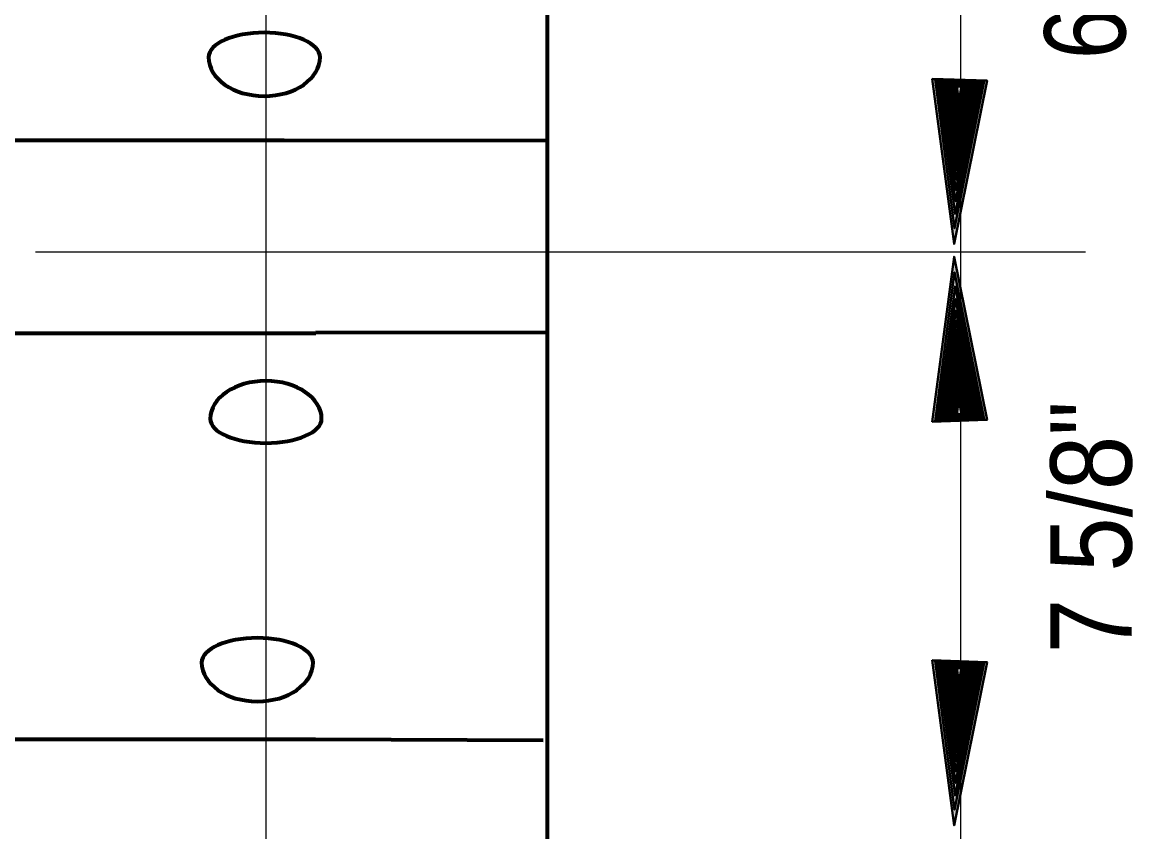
# Model space of a CAD drawing. Extents: x 895.6 to 930.4, y -2278.6 to -2254.7.
# Drawn here: x 918.313 to 920.071, y -2272.9 to -2271.618 of the extents above; entities that cross this region are included whole.
import ezdxf

# ---------------------------------------------------------------- set-up
doc = ezdxf.new("R2010")
doc.units = 0
doc.header["$LTSCALE"] = 0.051
doc.layers.add('1', color=7, linetype='Continuous', lineweight=70)
doc.layers.add('3', color=7, linetype='Continuous', lineweight=40)

msp = doc.modelspace()

# ---------------------------------------------------------------- hatches: boundary and pattern name
at = {"layer": '3'}
for points in [[(919.75367, -2271.708), (919.84033, -2271.71092), (919.78817, -2271.96933), (919.78817, -2271.96933)], [(919.758, -2271.70925), (919.836, -2271.712), (919.789, -2271.94458), (919.789, -2271.94458)], [(919.76192, -2271.7105), (919.832, -2271.71283), (919.78975, -2271.92217), (919.78975, -2271.92217)], [(919.76533, -2271.7115), (919.82842, -2271.71367), (919.79042, -2271.90217), (919.79042, -2271.90217)], [(919.76833, -2271.71242), (919.82517, -2271.71433), (919.791, -2271.88408), (919.791, -2271.88408)], [(919.77125, -2271.7135), (919.82233, -2271.71508), (919.7915, -2271.86783), (919.7915, -2271.86783)], [(919.77383, -2271.71417), (919.81975, -2271.71567), (919.792, -2271.85308), (919.792, -2271.85308)], [(919.776, -2271.715), (919.8175, -2271.71625), (919.7925, -2271.83983), (919.7925, -2271.83983)], [(919.778, -2271.71542), (919.81542, -2271.71675), (919.793, -2271.82808), (919.793, -2271.82808)], [(919.78, -2271.71617), (919.81367, -2271.71733), (919.79333, -2271.81725), (919.79333, -2271.81725)], [(919.7815, -2271.71658), (919.81183, -2271.71767), (919.79358, -2271.80767), (919.79358, -2271.80767)], [(919.78308, -2271.71708), (919.81025, -2271.71808), (919.794, -2271.79908), (919.794, -2271.79908)], [(919.78442, -2271.7175), (919.80892, -2271.71833), (919.79425, -2271.79117), (919.79425, -2271.79117)], [(919.78567, -2271.71808), (919.80775, -2271.71858), (919.79442, -2271.78425), (919.79442, -2271.78425)], [(919.78675, -2271.71825), (919.80658, -2271.71892), (919.79458, -2271.778), (919.79458, -2271.778)], [(919.78775, -2271.71867), (919.80558, -2271.71908), (919.79492, -2271.77233), (919.79492, -2271.77233)], [(919.78867, -2271.71883), (919.80475, -2271.71942), (919.79508, -2271.76725), (919.79508, -2271.76725)], [(919.7895, -2271.719), (919.80392, -2271.71958), (919.79525, -2271.76267), (919.79525, -2271.76267)], [(919.78992, -2271.71942), (919.80308, -2271.71967), (919.79525, -2271.75858), (919.79525, -2271.75858)], [(919.7905, -2271.71958), (919.80233, -2271.72), (919.79533, -2271.75492), (919.79533, -2271.75492)], [(919.791, -2271.71992), (919.80158, -2271.72033), (919.79517, -2271.75167), (919.79517, -2271.75167)], [(919.79158, -2271.71992), (919.801, -2271.72033), (919.79533, -2271.74858), (919.79533, -2271.74858)], [(919.79208, -2271.72008), (919.80058, -2271.72042), (919.79558, -2271.74583), (919.79558, -2271.74583)], [(919.7925, -2271.72033), (919.80008, -2271.7205), (919.7955, -2271.7435), (919.7955, -2271.7435)], [(919.75367, -2272.25083), (919.84033, -2272.24792), (919.78817, -2271.9895), (919.78817, -2271.9895)], [(919.758, -2272.24958), (919.836, -2272.24683), (919.789, -2272.01425), (919.789, -2272.01425)], [(919.76192, -2272.24833), (919.832, -2272.246), (919.78975, -2272.03667), (919.78975, -2272.03667)], [(919.76533, -2272.24733), (919.82842, -2272.24517), (919.79042, -2272.05667), (919.79042, -2272.05667)], [(919.76833, -2272.24642), (919.82517, -2272.2445), (919.791, -2272.07475), (919.791, -2272.07475)], [(919.77125, -2272.24533), (919.82233, -2272.24375), (919.7915, -2272.091), (919.7915, -2272.091)], [(919.77383, -2272.24467), (919.81975, -2272.24317), (919.792, -2272.10575), (919.792, -2272.10575)], [(919.776, -2272.24383), (919.8175, -2272.24258), (919.7925, -2272.119), (919.7925, -2272.119)], [(919.778, -2272.24342), (919.81542, -2272.24208), (919.793, -2272.13075), (919.793, -2272.13075)], [(919.78, -2272.24267), (919.81367, -2272.2415), (919.79333, -2272.14158), (919.79333, -2272.14158)], [(919.7815, -2272.24225), (919.81183, -2272.24117), (919.79358, -2272.15117), (919.79358, -2272.15117)], [(919.78308, -2272.24175), (919.81025, -2272.24075), (919.794, -2272.15975), (919.794, -2272.15975)], [(919.78442, -2272.24133), (919.80892, -2272.2405), (919.79425, -2272.16767), (919.79425, -2272.16767)], [(919.78567, -2272.24075), (919.80775, -2272.24025), (919.79442, -2272.17458), (919.79442, -2272.17458)], [(919.78675, -2272.24058), (919.80658, -2272.23992), (919.79458, -2272.18083), (919.79458, -2272.18083)], [(919.78775, -2272.24017), (919.80558, -2272.23975), (919.79492, -2272.1865), (919.79492, -2272.1865)], [(919.78867, -2272.24), (919.80475, -2272.23942), (919.79508, -2272.19158), (919.79508, -2272.19158)], [(919.7895, -2272.23983), (919.80392, -2272.23925), (919.79525, -2272.19617), (919.79525, -2272.19617)], [(919.78992, -2272.23942), (919.80308, -2272.23917), (919.79525, -2272.20025), (919.79525, -2272.20025)], [(919.7905, -2272.23925), (919.80233, -2272.23883), (919.79533, -2272.20392), (919.79533, -2272.20392)], [(919.791, -2272.23892), (919.80158, -2272.2385), (919.79517, -2272.20717), (919.79517, -2272.20717)], [(919.79158, -2272.23892), (919.801, -2272.2385), (919.79533, -2272.21025), (919.79533, -2272.21025)], [(919.79208, -2272.23875), (919.80058, -2272.23842), (919.79558, -2272.213), (919.79558, -2272.213)], [(919.7925, -2272.2385), (919.80008, -2272.23833), (919.7955, -2272.21533), (919.7955, -2272.21533)], [(919.75367, -2272.62817), (919.84033, -2272.63108), (919.78817, -2272.8895), (919.78817, -2272.8895)], [(919.758, -2272.62942), (919.836, -2272.63217), (919.789, -2272.86475), (919.789, -2272.86475)], [(919.76192, -2272.63067), (919.832, -2272.633), (919.78975, -2272.84233), (919.78975, -2272.84233)], [(919.76533, -2272.63167), (919.82842, -2272.63383), (919.79042, -2272.82233), (919.79042, -2272.82233)], [(919.76833, -2272.63258), (919.82517, -2272.6345), (919.791, -2272.80425), (919.791, -2272.80425)], [(919.77125, -2272.63367), (919.82233, -2272.63525), (919.7915, -2272.788), (919.7915, -2272.788)], [(919.77383, -2272.63433), (919.81975, -2272.63583), (919.792, -2272.77325), (919.792, -2272.77325)], [(919.776, -2272.63517), (919.8175, -2272.63642), (919.7925, -2272.76), (919.7925, -2272.76)], [(919.778, -2272.63558), (919.81542, -2272.63692), (919.793, -2272.74825), (919.793, -2272.74825)], [(919.78, -2272.63633), (919.81367, -2272.6375), (919.79333, -2272.73742), (919.79333, -2272.73742)], [(919.7815, -2272.63675), (919.81183, -2272.63783), (919.79358, -2272.72783), (919.79358, -2272.72783)], [(919.78308, -2272.63725), (919.81025, -2272.63825), (919.794, -2272.71925), (919.794, -2272.71925)], [(919.78442, -2272.63767), (919.80892, -2272.6385), (919.79425, -2272.71133), (919.79425, -2272.71133)], [(919.78567, -2272.63825), (919.80775, -2272.63875), (919.79442, -2272.70442), (919.79442, -2272.70442)], [(919.78675, -2272.63842), (919.80658, -2272.63908), (919.79458, -2272.69817), (919.79458, -2272.69817)], [(919.78775, -2272.63883), (919.80558, -2272.63925), (919.79492, -2272.6925), (919.79492, -2272.6925)], [(919.78867, -2272.639), (919.80475, -2272.63958), (919.79508, -2272.68742), (919.79508, -2272.68742)], [(919.7895, -2272.63917), (919.80392, -2272.63975), (919.79525, -2272.68283), (919.79525, -2272.68283)], [(919.78992, -2272.63958), (919.80308, -2272.63983), (919.79525, -2272.67875), (919.79525, -2272.67875)], [(919.7905, -2272.63975), (919.80233, -2272.64017), (919.79533, -2272.67508), (919.79533, -2272.67508)], [(919.791, -2272.64008), (919.80158, -2272.6405), (919.79517, -2272.67183), (919.79517, -2272.67183)], [(919.79158, -2272.64008), (919.801, -2272.6405), (919.79533, -2272.66875), (919.79533, -2272.66875)], [(919.79208, -2272.64025), (919.80058, -2272.64058), (919.79558, -2272.666), (919.79558, -2272.666)], [(919.7925, -2272.6405), (919.80008, -2272.64067), (919.7955, -2272.66367), (919.7955, -2272.66367)]]:
    msp.add_hatch(color=256, dxfattribs=at).paths.add_polyline_path(points)

# ---------------------------------------------------------------- linework, layer by layer
at = {"layer": '1', "lineweight": 25}
for p, q in [((918.69942, -2273.34217), (918.69942, -2270.69617)), ((919.79892, -2273.84467), (919.79892, -2271.02042)), ((918.33392, -2271.98208), (919.99592, -2271.98208))]:
    msp.add_line(p, q, dxfattribs=at)
at = {"layer": '1'}
for p, q in [((919.14467, -2273.83717), (919.14467, -2271.04083)), ((918.77767, -2272.111), (917.28567, -2272.111)), ((919.142, -2272.10983), (918.77767, -2272.1095))]:
    msp.add_line(p, q, dxfattribs=at)
for points in [[(917.2355, -2271.80542), (917.23517, -2271.80533), (918.72717, -2271.80533), (919.14617, -2271.80583)], [(917.28467, -2272.75292), (918.77667, -2272.75292), (919.13792, -2272.75483)]]:
    msp.add_lwpolyline(points, dxfattribs=at)
for centre, major_axis, ratio in [((918.69626, -2271.6739), (-0.08819, 0), 0.442883), ((918.69626, -2271.6739), (0.08819, 0), 0.696674), ((918.69884, -2272.24614), (-0.08819, 0), 0.679978), ((918.69884, -2272.24614), (0.08819, 0), 0.434256), ((918.68526, -2272.6319), (-0.08819, 0), 0.442883), ((918.68526, -2272.6319), (0.08819, 0), 0.696674)]:
    msp.add_ellipse(centre, major_axis=major_axis, ratio=ratio, start_param=3.1415927, end_param=6.2831853, dxfattribs=at)
at = {"layer": '3'}
for points in [[(919.75367, -2271.708), (919.84033, -2271.71092), (919.78817, -2271.96933), (919.78817, -2271.96933)], [(919.758, -2271.70925), (919.836, -2271.712), (919.789, -2271.94458), (919.789, -2271.94458)], [(919.76192, -2271.7105), (919.832, -2271.71283), (919.78975, -2271.92217), (919.78975, -2271.92217)], [(919.76533, -2271.7115), (919.82842, -2271.71367), (919.79042, -2271.90217), (919.79042, -2271.90217)], [(919.76833, -2271.71242), (919.82517, -2271.71433), (919.791, -2271.88408), (919.791, -2271.88408)], [(919.77125, -2271.7135), (919.82233, -2271.71508), (919.7915, -2271.86783), (919.7915, -2271.86783)], [(919.77383, -2271.71417), (919.81975, -2271.71567), (919.792, -2271.85308), (919.792, -2271.85308)], [(919.776, -2271.715), (919.8175, -2271.71625), (919.7925, -2271.83983), (919.7925, -2271.83983)], [(919.778, -2271.71542), (919.81542, -2271.71675), (919.793, -2271.82808), (919.793, -2271.82808)], [(919.78, -2271.71617), (919.81367, -2271.71733), (919.79333, -2271.81725), (919.79333, -2271.81725)], [(919.7815, -2271.71658), (919.81183, -2271.71767), (919.79358, -2271.80767), (919.79358, -2271.80767)], [(919.78308, -2271.71708), (919.81025, -2271.71808), (919.794, -2271.79908), (919.794, -2271.79908)], [(919.78442, -2271.7175), (919.80892, -2271.71833), (919.79425, -2271.79117), (919.79425, -2271.79117)], [(919.78567, -2271.71808), (919.80775, -2271.71858), (919.79442, -2271.78425), (919.79442, -2271.78425)], [(919.78675, -2271.71825), (919.80658, -2271.71892), (919.79458, -2271.778), (919.79458, -2271.778)], [(919.78775, -2271.71867), (919.80558, -2271.71908), (919.79492, -2271.77233), (919.79492, -2271.77233)], [(919.78867, -2271.71883), (919.80475, -2271.71942), (919.79508, -2271.76725), (919.79508, -2271.76725)], [(919.7895, -2271.719), (919.80392, -2271.71958), (919.79525, -2271.76267), (919.79525, -2271.76267)], [(919.78992, -2271.71942), (919.80308, -2271.71967), (919.79525, -2271.75858), (919.79525, -2271.75858)], [(919.7905, -2271.71958), (919.80233, -2271.72), (919.79533, -2271.75492), (919.79533, -2271.75492)], [(919.791, -2271.71992), (919.80158, -2271.72033), (919.79517, -2271.75167), (919.79517, -2271.75167)], [(919.79158, -2271.71992), (919.801, -2271.72033), (919.79533, -2271.74858), (919.79533, -2271.74858)], [(919.79208, -2271.72008), (919.80058, -2271.72042), (919.79558, -2271.74583), (919.79558, -2271.74583)], [(919.7925, -2271.72033), (919.80008, -2271.7205), (919.7955, -2271.7435), (919.7955, -2271.7435)], [(919.75367, -2272.25083), (919.84033, -2272.24792), (919.78817, -2271.9895), (919.78817, -2271.9895)], [(919.758, -2272.24958), (919.836, -2272.24683), (919.789, -2272.01425), (919.789, -2272.01425)], [(919.76192, -2272.24833), (919.832, -2272.246), (919.78975, -2272.03667), (919.78975, -2272.03667)], [(919.76533, -2272.24733), (919.82842, -2272.24517), (919.79042, -2272.05667), (919.79042, -2272.05667)], [(919.76833, -2272.24642), (919.82517, -2272.2445), (919.791, -2272.07475), (919.791, -2272.07475)], [(919.77125, -2272.24533), (919.82233, -2272.24375), (919.7915, -2272.091), (919.7915, -2272.091)], [(919.77383, -2272.24467), (919.81975, -2272.24317), (919.792, -2272.10575), (919.792, -2272.10575)], [(919.776, -2272.24383), (919.8175, -2272.24258), (919.7925, -2272.119), (919.7925, -2272.119)], [(919.778, -2272.24342), (919.81542, -2272.24208), (919.793, -2272.13075), (919.793, -2272.13075)], [(919.78, -2272.24267), (919.81367, -2272.2415), (919.79333, -2272.14158), (919.79333, -2272.14158)], [(919.7815, -2272.24225), (919.81183, -2272.24117), (919.79358, -2272.15117), (919.79358, -2272.15117)], [(919.78308, -2272.24175), (919.81025, -2272.24075), (919.794, -2272.15975), (919.794, -2272.15975)], [(919.78442, -2272.24133), (919.80892, -2272.2405), (919.79425, -2272.16767), (919.79425, -2272.16767)], [(919.78567, -2272.24075), (919.80775, -2272.24025), (919.79442, -2272.17458), (919.79442, -2272.17458)], [(919.78675, -2272.24058), (919.80658, -2272.23992), (919.79458, -2272.18083), (919.79458, -2272.18083)], [(919.78775, -2272.24017), (919.80558, -2272.23975), (919.79492, -2272.1865), (919.79492, -2272.1865)], [(919.78867, -2272.24), (919.80475, -2272.23942), (919.79508, -2272.19158), (919.79508, -2272.19158)], [(919.7895, -2272.23983), (919.80392, -2272.23925), (919.79525, -2272.19617), (919.79525, -2272.19617)], [(919.78992, -2272.23942), (919.80308, -2272.23917), (919.79525, -2272.20025), (919.79525, -2272.20025)], [(919.7905, -2272.23925), (919.80233, -2272.23883), (919.79533, -2272.20392), (919.79533, -2272.20392)], [(919.791, -2272.23892), (919.80158, -2272.2385), (919.79517, -2272.20717), (919.79517, -2272.20717)], [(919.79158, -2272.23892), (919.801, -2272.2385), (919.79533, -2272.21025), (919.79533, -2272.21025)], [(919.79208, -2272.23875), (919.80058, -2272.23842), (919.79558, -2272.213), (919.79558, -2272.213)], [(919.7925, -2272.2385), (919.80008, -2272.23833), (919.7955, -2272.21533), (919.7955, -2272.21533)], [(919.75367, -2272.62817), (919.84033, -2272.63108), (919.78817, -2272.8895), (919.78817, -2272.8895)], [(919.758, -2272.62942), (919.836, -2272.63217), (919.789, -2272.86475), (919.789, -2272.86475)], [(919.76192, -2272.63067), (919.832, -2272.633), (919.78975, -2272.84233), (919.78975, -2272.84233)], [(919.76533, -2272.63167), (919.82842, -2272.63383), (919.79042, -2272.82233), (919.79042, -2272.82233)], [(919.76833, -2272.63258), (919.82517, -2272.6345), (919.791, -2272.80425), (919.791, -2272.80425)], [(919.77125, -2272.63367), (919.82233, -2272.63525), (919.7915, -2272.788), (919.7915, -2272.788)], [(919.77383, -2272.63433), (919.81975, -2272.63583), (919.792, -2272.77325), (919.792, -2272.77325)], [(919.776, -2272.63517), (919.8175, -2272.63642), (919.7925, -2272.76), (919.7925, -2272.76)], [(919.778, -2272.63558), (919.81542, -2272.63692), (919.793, -2272.74825), (919.793, -2272.74825)], [(919.78, -2272.63633), (919.81367, -2272.6375), (919.79333, -2272.73742), (919.79333, -2272.73742)], [(919.7815, -2272.63675), (919.81183, -2272.63783), (919.79358, -2272.72783), (919.79358, -2272.72783)], [(919.78308, -2272.63725), (919.81025, -2272.63825), (919.794, -2272.71925), (919.794, -2272.71925)], [(919.78442, -2272.63767), (919.80892, -2272.6385), (919.79425, -2272.71133), (919.79425, -2272.71133)], [(919.78567, -2272.63825), (919.80775, -2272.63875), (919.79442, -2272.70442), (919.79442, -2272.70442)], [(919.78675, -2272.63842), (919.80658, -2272.63908), (919.79458, -2272.69817), (919.79458, -2272.69817)], [(919.78775, -2272.63883), (919.80558, -2272.63925), (919.79492, -2272.6925), (919.79492, -2272.6925)], [(919.78867, -2272.639), (919.80475, -2272.63958), (919.79508, -2272.68742), (919.79508, -2272.68742)], [(919.7895, -2272.63917), (919.80392, -2272.63975), (919.79525, -2272.68283), (919.79525, -2272.68283)], [(919.78992, -2272.63958), (919.80308, -2272.63983), (919.79525, -2272.67875), (919.79525, -2272.67875)], [(919.7905, -2272.63975), (919.80233, -2272.64017), (919.79533, -2272.67508), (919.79533, -2272.67508)], [(919.791, -2272.64008), (919.80158, -2272.6405), (919.79517, -2272.67183), (919.79517, -2272.67183)], [(919.79158, -2272.64008), (919.801, -2272.6405), (919.79533, -2272.66875), (919.79533, -2272.66875)], [(919.79208, -2272.64025), (919.80058, -2272.64058), (919.79558, -2272.666), (919.79558, -2272.666)], [(919.7925, -2272.6405), (919.80008, -2272.64067), (919.7955, -2272.66367), (919.7955, -2272.66367)]]:
    msp.add_lwpolyline(points, close=True, dxfattribs=at)

# ---------------------------------------------------------------- texts
at = {"layer": '1'}
for s, width, p in [('6 3/16"', 0.85, (920.05942, -2271.67708)), ('7 5/8"', 0.9, (920.06917, -2272.61717))]:
    msp.add_text(s, height=0.1286, rotation=90, dxfattribs=dict(at, width=width)).set_placement(p)

doc.saveas('drawing.dxf')
